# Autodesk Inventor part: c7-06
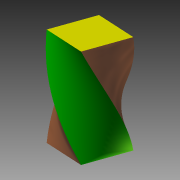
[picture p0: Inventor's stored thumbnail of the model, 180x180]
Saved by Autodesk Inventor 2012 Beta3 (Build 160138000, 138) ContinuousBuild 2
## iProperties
Created: 2010-12
Part Number: c7-06
Material: Copper
Document SubType Name: Modeling
Designer: Beta-8540w
Density: 8.94 g/cm^3
Author: Beta-8540w
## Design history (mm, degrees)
sketch "Sketch1"
  geometry: L1 (30, 30)-(30, -30); L2 (30, -30)-(-30, -30); L3 (-30, -30)-(-30, 30); L4 (-30, 30)-(30, 30); L5 (0, 0)-(30, 30); 1 further point
  constraints: 10 end point, 1 coincident, 1 horizontal, 9 other
  dimensions: "d1" = 60 distance of L3.end L1.start; "d2" = 42.42641 distance of L5.start L1.start (derived)
sketch "Sketch2"
  geometry: L1 (0, 0)-(0, 120)
  constraints: 2 end point, 1 vertical
  dimensions: "d3" = 120 distance of L1.start L1.end
sketch "3D Sketch1"
sweep "Sweep1" sketch "Sketch1", "Sketch2", "3D Sketch1" dims "d8" = 0
body "Solid1"
node "Helical Curve1" dims "d4" = 120, "d5" = 2.5, "d6" = 84.85281 (= 2 x d2), "d7" = 0
